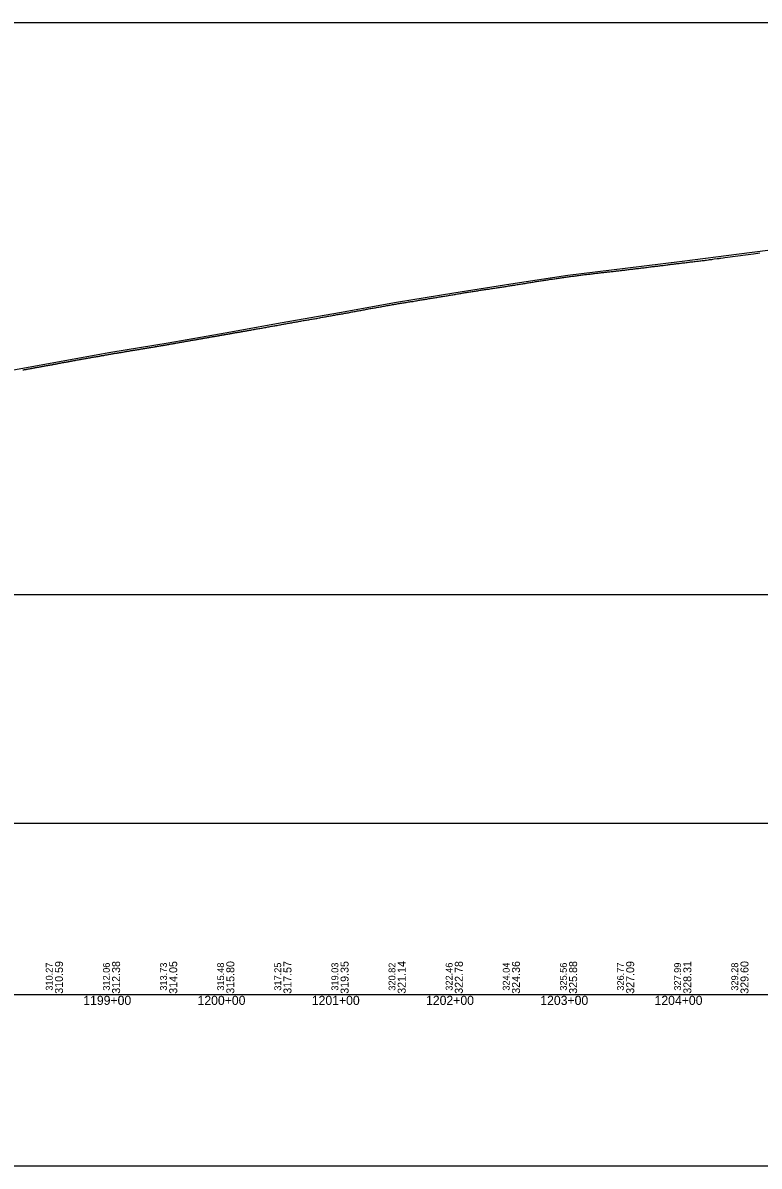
# Model space of a CAD drawing. Extents: x 2898 to 49495, y -15038 to -13538.
# Drawn here: x 9176 to 9821, y -15038 to -14038 of the extents above; entities that cross this region are included whole.
import ezdxf

# ---------------------------------------------------------------- set-up
doc = ezdxf.new("R2010")
doc.units = 0
for name, color, linetype in [('RD_DDB_Profile_EX', 7, 'Continuous'), ('RD_DDB_Profile_PR', 7, 'Continuous'), ('RD_DDB_StaTX', 7, 'Continuous'), ('RD_DDB_StripGrade', 7, 'Continuous'), ('RD_GPK_Profile_Cell', 7, 'Continuous'), ('RD_SHT_ShtClip', 7, 'Continuous')]:
    doc.layers.add(name, color=color, linetype=linetype)

msp = doc.modelspace()

# ---------------------------------------------------------------- linework, layer by layer
at = {"layer": 'RD_DDB_Profile_EX'}
for points in [[(9785.71, -14244.45), (9786.45, -14244.34), (9787.27, -14244.34), (9789.2, -14243.87), (9790.69, -14243.65), (9810.98, -14241.14), (9815.73, -14240.43), (9821.41, -14239.73)], [(9684.74, -14256.77), (9685.74, -14256.66), (9686.74, -14256.55), (9687.54, -14256.43), (9688.09, -14256.36), (9689.08, -14256.3), (9690.09, -14256.27), (9691.09, -14255.99), (9692.08, -14255.93), (9693.08, -14255.87), (9694.09, -14255.68), (9695.18, -14255.56), (9695.99, -14255.47), (9697.18, -14255.32), (9697.99, -14255.27), (9699.18, -14255.18), (9700.18, -14255.05), (9701.18, -14254.87), (9701.98, -14254.78), (9703.18, -14254.66), (9704.18, -14254.53), (9704.98, -14254.41), (9706.18, -14254.29), (9706.99, -14254.17), (9708.17, -14254.02), (9708.98, -14253.94), (9710.18, -14253.8), (9710.98, -14253.68), (9712.17, -14253.57), (9713.18, -14253.4), (9713.98, -14253.32), (9715.17, -14253.19), (9716.18, -14253.04), (9717.18, -14252.94), (9717.98, -14252.82), (9719.17, -14252.69), (9719.99, -14252.61), (9721.17, -14252.42), (9722.17, -14252.33), (9723.17, -14252.23), (9723.98, -14252.07), (9724.98, -14251.96), (9726.17, -14251.73), (9726.98, -14251.69), (9728.17, -14251.6), (9729.17, -14251.63), (9730.16, -14251.36), (9730.98, -14251.28), (9732.17, -14251.16), (9732.98, -14251.12), (9733.79, -14250.97), (9734.78, -14250.82), (9735.79, -14250.72), (9736.79, -14250.58), (9737.79, -14250.48), (9738.79, -14250.33), (9739.79, -14250.15), (9740.79, -14250.04), (9741.78, -14249.9), (9742.79, -14249.87), (9743.79, -14249.65), (9744.78, -14249.55), (9745.79, -14249.4), (9746.79, -14249.3), (9747.79, -14249.23), (9748.78, -14249.04), (9749.79, -14248.93), (9750.79, -14248.83), (9751.78, -14248.72), (9752.79, -14248.59), (9753.79, -14248.45), (9754.79, -14248.3), (9755.78, -14248.28), (9756.79, -14248.17), (9757.79, -14248.03), (9758.78, -14247.83), (9759.78, -14247.73), (9760.79, -14247.62), (9761.78, -14247.51), (9762.78, -14247.37), (9763.78, -14247.26), (9764.79, -14247.11), (9765.78, -14246.97), (9766.78, -14246.9), (9767.79, -14246.76), (9768.78, -14246.6), (9769.78, -14246.54), (9770.8, -14246.34), (9771.8, -14246.3), (9772.79, -14246.37), (9773.8, -14245.99), (9774.8, -14245.91), (9776.27, -14245.66), (9777.27, -14245.56), (9778.28, -14245.42), (9779.27, -14245.33), (9780.27, -14245.06), (9781.46, -14244.89), (9784.09, -14244.57), (9784.9, -14244.53), (9785.71, -14244.45)], [(9585.43, -14271.09), (9586.44, -14270.91), (9587.43, -14270.81), (9588.43, -14270.62), (9589.43, -14270.44), (9590.43, -14270.29), (9591.43, -14270.17), (9592.42, -14269.99), (9593.43, -14269.85), (9594.43, -14269.61), (9595.42, -14269.51), (9596.43, -14269.34), (9597.42, -14269.22), (9598.42, -14269.08), (9599.42, -14268.92), (9600.42, -14268.73), (9601.42, -14268.6), (9602.42, -14268.43), (9603.41, -14268.27), (9604.42, -14268.13), (9605.22, -14267.97), (9605.9, -14267.9), (9606.91, -14267.77), (9607.91, -14267.55), (9608.9, -14267.34), (9609.9, -14267.2), (9610.91, -14267.06), (9611.9, -14266.94), (9612.9, -14266.76), (9613.91, -14266.63), (9614.9, -14266.48), (9615.98, -14266.32), (9616.98, -14266.2), (9617.97, -14265.94), (9618.98, -14265.74), (9619.97, -14265.65), (9620.97, -14265.52), (9621.97, -14265.37), (9622.97, -14265.22), (9623.97, -14265.06), (9624.97, -14264.8), (9625.97, -14264.69), (9626.97, -14264.47), (9627.97, -14264.4), (9628.96, -14264.25), (9629.97, -14264.17), (9630.97, -14263.83), (9631.96, -14263.78), (9632.97, -14263.64), (9633.97, -14263.44), (9634.96, -14263.31), (9635.96, -14263.11), (9636.97, -14263.07), (9637.96, -14262.77), (9638.96, -14262.66), (9639.96, -14262.56), (9640.96, -14262.41), (9641.96, -14262.3), (9642.96, -14262.15), (9643.96, -14261.97), (9644.96, -14261.8), (9645.95, -14261.69), (9646.95, -14261.54), (9647.75, -14261.4), (9648.75, -14261.3), (9649.75, -14261.18), (9650.74, -14260.99), (9651.75, -14260.92), (9652.75, -14260.73), (9653.74, -14260.66), (9654.74, -14260.39), (9655.75, -14260.29), (9656.75, -14260.1), (9657.74, -14260.02), (9658.74, -14259.89), (9659.75, -14259.75), (9660.74, -14259.62), (9661.74, -14259.46), (9662.75, -14259.35), (9663.74, -14259.29), (9664.74, -14259.1), (9665.74, -14258.96), (9666.75, -14258.85), (9667.74, -14258.71), (9668.74, -14258.6), (9669.74, -14258.49), (9670.74, -14258.35), (9671.74, -14258.27), (9672.74, -14258.13), (9673.75, -14257.98), (9674.74, -14257.87), (9675.74, -14257.77), (9676.74, -14257.62), (9677.74, -14257.46), (9678.74, -14257.36), (9679.74, -14257.3), (9680.74, -14257.21), (9681.74, -14257.1), (9682.74, -14256.93), (9683.74, -14256.87), (9684.74, -14256.77)], [(9485.95, -14287.43), (9486.95, -14287.18), (9487.95, -14287.02), (9488.95, -14286.89), (9489.91, -14286.75), (9490.9, -14286.49), (9491.9, -14286.33), (9492.91, -14286.15), (9493.9, -14286), (9494.9, -14285.81), (9495.91, -14285.59), (9496.9, -14285.45), (9497.9, -14285.25), (9498.9, -14285.15), (9499.9, -14284.91), (9500.9, -14284.77), (9501.9, -14284.65), (9502.9, -14284.47), (9503.9, -14284.28), (9504.89, -14284.07), (9505.89, -14283.91), (9506.89, -14283.71), (9507.89, -14283.56), (9508.89, -14283.46), (9509.89, -14283.31), (9510.89, -14283.09), (9511.88, -14282.92), (9512.89, -14282.77), (9513.89, -14282.55), (9514.88, -14282.47), (9515.89, -14282.3), (9516.89, -14282.24), (9517.88, -14282.18), (9518.88, -14281.75), (9519.88, -14281.63), (9520.88, -14281.5), (9521.88, -14281.45), (9522.88, -14281.11), (9523.88, -14281), (9524.76, -14280.84), (9525.76, -14280.64), (9526.76, -14280.48), (9527.76, -14280.34), (9528.76, -14280.22), (9529.75, -14280), (9530.75, -14279.81), (9531.76, -14279.66), (9532.75, -14279.53), (9533.75, -14279.37), (9534.76, -14279.18), (9535.71, -14279.06), (9536.71, -14278.84), (9537.7, -14278.74), (9538.71, -14278.6), (9539.71, -14278.38), (9540.7, -14278.17), (9541.7, -14278.05), (9542.7, -14277.94), (9543.7, -14277.88), (9544.7, -14277.53), (9545.7, -14277.42), (9546.7, -14277.23), (9547.69, -14277.1), (9548.7, -14276.92), (9549.7, -14276.72), (9550.69, -14276.6), (9551.69, -14276.46), (9552.7, -14276.26), (9553.69, -14276.13), (9554.69, -14275.95), (9555.69, -14275.78), (9556.69, -14275.59), (9557.69, -14275.42), (9558.69, -14275.19), (9559.69, -14275.04), (9560.68, -14274.86), (9561.68, -14274.71), (9562.69, -14274.57), (9563.45, -14274.37), (9564.45, -14274.24), (9565.45, -14274.08), (9566.45, -14273.98), (9567.44, -14273.83), (9568.45, -14273.66), (9569.45, -14273.46), (9570.44, -14273.35), (9571.45, -14273.2), (9572.45, -14273.01), (9573.44, -14272.87), (9574.44, -14272.72), (9575.44, -14272.54), (9576.44, -14272.39), (9577.44, -14272.25), (9578.43, -14272.09), (9579.44, -14271.98), (9580.44, -14271.82), (9581.43, -14271.79), (9582.44, -14271.52), (9583.44, -14271.4), (9584.43, -14271.26), (9585.43, -14271.09)], [(9386.76, -14305.19), (9387.76, -14305.07), (9388.82, -14304.87), (9389.83, -14304.62), (9390.83, -14304.48), (9391.82, -14304.25), (9392.83, -14304.03), (9393.82, -14303.9), (9394.82, -14303.73), (9395.82, -14303.54), (9396.82, -14303.39), (9397.82, -14303.18), (9398.82, -14303.04), (9399.82, -14302.81), (9400.82, -14302.66), (9401.81, -14302.5), (9402.81, -14302.28), (9403.82, -14302.13), (9404.81, -14301.97), (9405.6, -14301.83), (9406.6, -14301.71), (9407.6, -14301.38), (9408.6, -14301.26), (9409.59, -14301.1), (9410.6, -14300.93), (9411.6, -14300.86), (9412.59, -14300.62), (9413.6, -14300.36), (9414.6, -14300.22), (9415.59, -14299.99), (9416.6, -14299.84), (9417.59, -14299.62), (9418.59, -14299.51), (9419.6, -14299.38), (9420.59, -14299.18), (9421.59, -14298.93), (9422.59, -14298.77), (9423.59, -14298.62), (9424.59, -14298.45), (9425.59, -14298.31), (9426.59, -14298.16), (9427.59, -14297.94), (9428.58, -14297.69), (9429.59, -14297.54), (9430.58, -14297.42), (9431.58, -14297.25), (9432.59, -14297.11), (9433.58, -14296.91), (9434.58, -14296.72), (9435.59, -14296.5), (9436.23, -14296.35), (9437.23, -14296.17), (9438.24, -14296.02), (9439.23, -14295.87), (9440.23, -14295.68), (9441.23, -14295.5), (9442.23, -14295.34), (9443.23, -14295.11), (9444.23, -14294.96), (9445.23, -14294.73), (9446.22, -14294.65), (9447.22, -14294.42), (9448.23, -14294.22), (9449.22, -14294.07), (9450.22, -14293.88), (9451.22, -14293.68), (9452.22, -14293.57), (9453.22, -14293.36), (9454.22, -14293.13), (9455.22, -14293.01), (9456.22, -14292.89), (9457.21, -14292.65), (9458.22, -14292.47), (9459.21, -14292.33), (9460.21, -14292.14), (9461.22, -14292), (9462.21, -14291.75), (9463.21, -14291.55), (9464.21, -14291.35), (9465.21, -14291.2), (9466.21, -14291.02), (9467.2, -14290.86), (9468.21, -14290.59), (9469.21, -14290.4), (9470.2, -14290.28), (9471.21, -14290.06), (9472.2, -14289.95), (9473.2, -14289.75), (9474.21, -14289.53), (9475.2, -14289.41), (9476.2, -14289.25), (9476.96, -14288.98), (9477.96, -14288.8), (9478.96, -14288.66), (9479.96, -14288.44), (9480.96, -14288.26), (9481.96, -14288.11), (9482.95, -14287.97), (9483.96, -14287.79), (9484.96, -14287.59), (9485.95, -14287.43)], [(9332.27, -14314.71), (9332.96, -14314.61), (9333.27, -14314.56), (9333.96, -14314.42), (9334.28, -14314.39), (9334.96, -14314.29), (9335.27, -14314.23), (9335.96, -14314.09), (9336.27, -14314.03), (9336.96, -14313.92), (9337.28, -14313.88), (9337.96, -14313.7), (9338.27, -14313.66), (9338.96, -14313.59), (9339.27, -14313.49), (9339.95, -14313.43), (9340.26, -14313.38), (9340.95, -14313.21), (9341.27, -14313.14), (9341.96, -14312.97), (9342.27, -14312.91), (9342.95, -14312.81), (9343.26, -14312.76), (9343.95, -14312.66), (9344.48, -14312.62), (9344.79, -14312.56), (9345.48, -14312.42), (9345.79, -14312.39), (9346.48, -14312.29), (9346.79, -14312.24), (9347.48, -14312.11), (9347.79, -14312.06), (9348.47, -14311.95), (9348.78, -14311.85), (9349.48, -14311.67), (9349.79, -14311.61), (9350.48, -14311.51), (9350.79, -14311.46), (9351.47, -14311.39), (9351.78, -14311.34), (9352.48, -14311.24), (9352.79, -14311.18), (9353.48, -14311.04), (9353.79, -14310.98), (9354.47, -14310.77), (9354.78, -14310.72), (9355.47, -14310.65), (9355.78, -14310.61), (9356.47, -14310.5), (9356.78, -14310.47), (9357.47, -14310.33), (9357.78, -14310.24), (9358.47, -14310.14), (9358.78, -14310.08), (9359.47, -14309.94), (9359.78, -14309.91), (9360.47, -14309.77), (9360.78, -14309.69), (9361.47, -14309.59), (9361.78, -14309.54), (9362.47, -14309.44), (9362.77, -14309.38), (9363.47, -14309.24), (9363.78, -14309.19), (9364.47, -14309.05), (9364.78, -14309.04), (9365.47, -14308.97), (9365.77, -14308.89), (9366.47, -14308.75), (9366.77, -14308.7), (9367.47, -14308.57), (9367.78, -14308.5), (9368.47, -14308.36), (9368.77, -14308.33), (9369.47, -14308.26), (9369.77, -14308.25), (9370.47, -14308.11), (9370.77, -14307.99), (9371.47, -14307.88), (9371.77, -14307.82), (9372.47, -14307.72), (9372.77, -14307.64), (9373.47, -14307.57), (9373.77, -14307.51), (9374.76, -14307.36), (9375.47, -14307.22), (9375.77, -14307.19), (9376.47, -14307.05), (9376.77, -14307.01), (9377.76, -14306.79), (9378.47, -14306.62), (9378.77, -14306.59), (9379.47, -14306.45), (9379.77, -14306.43), (9380.76, -14306.22), (9381.76, -14306.08), (9382.77, -14305.91), (9383.76, -14305.79), (9384.76, -14305.54), (9385.76, -14305.44), (9386.76, -14305.19)], [(9281.87, -14323.41), (9282.19, -14323.38), (9282.87, -14323.35), (9283.19, -14323.24), (9283.86, -14323), (9284.18, -14322.97), (9284.87, -14322.9), (9285.18, -14322.83), (9286.11, -14322.66), (9286.43, -14322.63), (9287.11, -14322.53), (9287.43, -14322.48), (9288.11, -14322.41), (9288.42, -14322.35), (9289.11, -14322.21), (9289.42, -14322.13), (9290.11, -14322.03), (9290.43, -14322), (9291.1, -14321.86), (9291.42, -14321.8), (9292.1, -14321.73), (9292.42, -14321.65), (9293.11, -14321.48), (9293.42, -14321.42), (9294.1, -14321.32), (9294.42, -14321.28), (9295.1, -14321.18), (9295.42, -14321.15), (9296.3, -14321.03), (9296.99, -14320.89), (9297.3, -14320.81), (9297.99, -14320.75), (9298.3, -14320.68), (9298.98, -14320.55), (9299.3, -14320.51), (9299.98, -14320.38), (9300.3, -14320.33), (9300.98, -14320.26), (9301.3, -14320.18), (9301.98, -14320.01), (9302.3, -14319.96), (9302.98, -14319.9), (9303.3, -14319.85), (9303.98, -14319.71), (9304.3, -14319.62), (9304.98, -14319.51), (9305.29, -14319.47), (9305.98, -14319.3), (9306.3, -14319.28), (9306.98, -14319.18), (9307.29, -14319.08), (9307.98, -14318.98), (9308.29, -14318.95), (9308.98, -14318.81), (9309.3, -14318.76), (9309.97, -14318.63), (9310.29, -14318.58), (9310.97, -14318.44), (9311.29, -14318.36), (9311.98, -14318.29), (9312.29, -14318.25), (9312.97, -14318.14), (9313.29, -14318.1), (9313.97, -14317.89), (9314.29, -14317.83), (9314.98, -14317.79), (9315.29, -14317.73), (9315.97, -14317.56), (9316.29, -14317.5), (9316.97, -14317.43), (9317.29, -14317.4), (9317.97, -14317.23), (9318.28, -14317.15), (9318.97, -14317.01), (9319.28, -14316.96), (9319.97, -14316.89), (9320.29, -14316.83), (9320.97, -14316.73), (9321.28, -14316.7), (9321.97, -14316.52), (9322.28, -14316.46), (9322.97, -14316.32), (9323.29, -14316.25), (9323.97, -14316.14), (9324.28, -14316.11), (9324.97, -14315.97), (9325.28, -14315.93), (9325.97, -14315.79), (9326.28, -14315.74), (9326.97, -14315.64), (9327.28, -14315.58), (9327.96, -14315.47), (9328.28, -14315.4), (9328.96, -14315.29), (9329.27, -14315.26), (9329.96, -14315.09), (9330.28, -14315.03), (9330.96, -14314.92), (9331.28, -14314.88), (9331.96, -14314.77), (9332.27, -14314.71)], [(9231.77, -14331.91), (9232.09, -14331.88), (9232.77, -14331.78), (9233.09, -14331.67), (9233.76, -14331.57), (9234.08, -14331.53), (9234.76, -14331.43), (9235.09, -14331.43), (9235.76, -14331.23), (9236.08, -14331.07), (9236.76, -14331), (9237.08, -14330.98), (9237.76, -14330.91), (9238.08, -14330.88), (9238.76, -14330.71), (9239.08, -14330.6), (9239.76, -14330.53), (9240.08, -14330.52), (9240.76, -14330.38), (9241.08, -14330.32), (9241.76, -14330.21), (9242.08, -14330.15), (9242.76, -14329.98), (9243.08, -14329.92), (9243.76, -14329.88), (9244.07, -14329.85), (9244.76, -14329.64), (9245.07, -14329.53), (9245.76, -14329.46), (9246.08, -14329.43), (9246.76, -14329.33), (9247.07, -14329.27), (9247.76, -14329.13), (9248.07, -14329.07), (9248.76, -14328.93), (9249.08, -14328.9), (9249.9, -14328.76), (9250.22, -14328.73), (9250.9, -14328.66), (9251.21, -14328.55), (9251.89, -14328.35), (9252.21, -14328.32), (9252.9, -14328.21), (9253.21, -14328.17), (9253.9, -14328.1), (9254.21, -14328.03), (9254.89, -14327.86), (9255.21, -14327.8), (9255.89, -14327.7), (9256.21, -14327.65), (9256.9, -14327.51), (9257.21, -14327.48), (9257.89, -14327.38), (9258.21, -14327.33), (9258.89, -14327.23), (9259.21, -14327.17), (9259.89, -14327.06), (9260.2, -14327), (9260.89, -14326.83), (9261.21, -14326.8), (9261.89, -14326.73), (9262.21, -14326.67), (9262.88, -14326.56), (9263.2, -14326.52), (9263.89, -14326.38), (9264.2, -14326.36), (9264.89, -14326.19), (9265.2, -14326.1), (9265.88, -14326), (9266.2, -14325.95), (9266.88, -14325.78), (9267.2, -14325.73), (9267.88, -14325.73), (9268.2, -14325.68), (9268.88, -14325.58), (9269.2, -14325.53), (9269.88, -14325.4), (9270.2, -14325.32), (9270.88, -14325.18), (9271.19, -14325.15), (9271.88, -14325.08), (9272.2, -14325.02), (9272.88, -14324.85), (9273.2, -14324.8), (9273.88, -14324.73), (9274.19, -14324.7), (9274.88, -14324.56), (9275.2, -14324.5), (9275.87, -14324.46), (9276.19, -14324.4), (9276.88, -14324.16), (9277.19, -14324.11), (9277.88, -14324.08), (9278.19, -14324.03), (9278.87, -14323.83), (9279.19, -14323.8), (9279.87, -14323.69), (9280.19, -14323.66), (9280.87, -14323.56), (9281.18, -14323.48), (9281.87, -14323.41)], [(9181.86, -14341.07), (9182.21, -14340.98), (9182.86, -14340.88), (9183.21, -14340.81), (9183.86, -14340.65), (9184.21, -14340.6), (9184.86, -14340.5), (9185.21, -14340.46), (9185.86, -14340.33), (9186.21, -14340.19), (9186.86, -14340.06), (9187.2, -14340.04), (9187.86, -14339.88), (9188.21, -14339.81), (9188.86, -14339.71), (9189.2, -14339.69), (9189.86, -14339.56), (9190.2, -14339.49), (9190.86, -14339.39), (9191.2, -14339.29), (9191.86, -14339.19), (9192.2, -14339.14), (9192.86, -14339.01), (9193.2, -14338.96), (9193.86, -14338.82), (9194.2, -14338.77), (9194.86, -14338.64), (9195.2, -14338.57), (9195.86, -14338.47), (9196.2, -14338.4), (9196.86, -14338.24), (9197.2, -14338.19), (9197.86, -14338.12), (9198.2, -14338.07), (9198.86, -14337.94), (9199.2, -14337.89), (9199.86, -14337.79), (9200.2, -14337.69), (9200.86, -14337.62), (9201.19, -14337.6), (9201.86, -14337.53), (9202.2, -14337.42), (9202.86, -14337.18), (9203.19, -14337.13), (9203.86, -14337.03), (9204.19, -14337), (9204.86, -14336.9), (9205.19, -14336.83), (9205.86, -14336.7), (9206.19, -14336.65), (9206.86, -14336.51), (9207.19, -14336.41), (9207.86, -14336.25), (9208.19, -14336.2), (9208.86, -14336.06), (9209.19, -14336), (9209.86, -14335.89), (9210.19, -14335.83), (9210.86, -14335.66), (9211.18, -14335.59), (9211.86, -14335.49), (9212.19, -14335.41), (9212.86, -14335.28), (9213.18, -14335.24), (9213.86, -14335.17), (9214.18, -14335.11), (9214.86, -14335.01), (9215.19, -14334.94), (9215.86, -14334.81), (9216.18, -14334.76), (9216.86, -14334.55), (9217.18, -14334.52), (9217.85, -14334.42), (9218.18, -14334.35), (9218.77, -14334.29), (9219.1, -14334.22), (9219.77, -14334.09), (9220.1, -14334.02), (9220.77, -14333.92), (9221.09, -14333.89), (9221.77, -14333.79), (9222.1, -14333.7), (9222.77, -14333.57), (9223.09, -14333.52), (9223.77, -14333.35), (9224.09, -14333.27), (9224.77, -14333.17), (9225.1, -14333.1), (9225.77, -14332.93), (9226.09, -14332.9), (9226.77, -14332.8), (9227.09, -14332.75), (9227.77, -14332.65), (9228.09, -14332.57), (9228.77, -14332.47), (9229.09, -14332.4), (9229.77, -14332.27), (9230.09, -14332.22), (9230.76, -14332.12), (9231.08, -14332.08), (9231.77, -14331.91)], [(9176.22, -14342), (9176.86, -14341.94), (9177.21, -14341.88), (9177.86, -14341.75), (9178.22, -14341.7), (9178.86, -14341.6), (9179.21, -14341.55), (9179.86, -14341.42), (9180.21, -14341.35), (9180.87, -14341.22), (9181.22, -14341.17), (9181.86, -14341.07)]]:
    msp.add_lwpolyline(points, dxfattribs=at)
at = {"layer": 'RD_DDB_Profile_PR'}
msp.add_lwpolyline([(9153.38, -14344.62), (9203.38, -14335.5), (9253.38, -14326.55), (9303.38, -14318.23), (9353.38, -14309.46), (9403.38, -14300.59), (9453.38, -14291.72), (9503.38, -14282.78), (9553.38, -14274.57), (9603.38, -14266.68), (9653.38, -14259.08), (9703.38, -14253.03), (9753.38, -14246.91), (9803.38, -14240.48), (9853.38, -14233.96)], dxfattribs=at)
at = {"layer": 'RD_GPK_Profile_Cell'}
msp.add_line((2976.05, -14888.47), (48721.13, -14888.47), dxfattribs=at)
at = {"layer": 'RD_SHT_ShtClip'}
for points in [[(10476.22, -14538.47), (10476.22, -14038.47), (10476.22, -14038.47), (8976.38, -14038.47), (8976.38, -14538.47)], [(8956.38, -14738.47), (10496.05, -14738.47), (10496.05, -15038.47), (8956.38, -15038.47)]]:
    msp.add_lwpolyline(points, close=True, dxfattribs=at)

# ---------------------------------------------------------------- texts
at = {"layer": 'RD_DDB_StaTX'}
for s, p in [('1199+00', (9229.18, -14897.47)), ('1200+00', (9329.18, -14897.47)), ('1201+00', (9429.18, -14897.47)), ('1202+00', (9529.18, -14897.47)), ('1203+00', (9629.18, -14897.47)), ('1204+00', (9729.18, -14897.47))]:
    msp.add_text(s, height=8, dxfattribs=at).set_placement(p)
at = {"layer": 'RD_DDB_StripGrade'}
for s, height, p in [('310.59', 7, (9211.38, -14887.72)), ('312.38', 7, (9261.38, -14887.72)), ('314.05', 7, (9311.38, -14887.72)), ('315.80', 7, (9361.38, -14887.72)), ('317.57', 7, (9411.38, -14887.72)), ('319.35', 7, (9461.38, -14887.72)), ('321.14', 7, (9511.38, -14887.72)), ('322.78', 7, (9561.38, -14887.72)), ('324.36', 7, (9611.38, -14887.72)), ('325.88', 7, (9661.38, -14887.72)), ('327.09', 7, (9711.38, -14887.72)), ('328.31', 7, (9761.38, -14887.72)), ('329.60', 7, (9811.38, -14887.72)), ('310.27', 6, (9202.38, -14884.98)), ('312.06', 6, (9252.38, -14884.98)), ('313.73', 6, (9302.38, -14884.98)), ('315.48', 6, (9352.38, -14884.98)), ('317.25', 6, (9402.38, -14884.98)), ('319.03', 6, (9452.38, -14884.98)), ('320.82', 6, (9502.38, -14884.98)), ('322.46', 6, (9552.38, -14884.98)), ('324.04', 6, (9602.38, -14884.98)), ('325.56', 6, (9652.38, -14884.98)), ('326.77', 6, (9702.38, -14884.98)), ('327.99', 6, (9752.38, -14884.98)), ('329.28', 6, (9802.38, -14884.98))]:
    msp.add_text(s, height=height, rotation=90, dxfattribs=at).set_placement(p)

doc.saveas('drawing.dxf')
